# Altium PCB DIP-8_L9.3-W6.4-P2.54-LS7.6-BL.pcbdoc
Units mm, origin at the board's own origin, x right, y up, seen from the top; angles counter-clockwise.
Board outline 22.59 x 22.36 mm, 2 copper layers (Top Layer, Bottom Layer), stack 0 mm thick; 1 components, 0 nets, 8 pads, 0 vias.
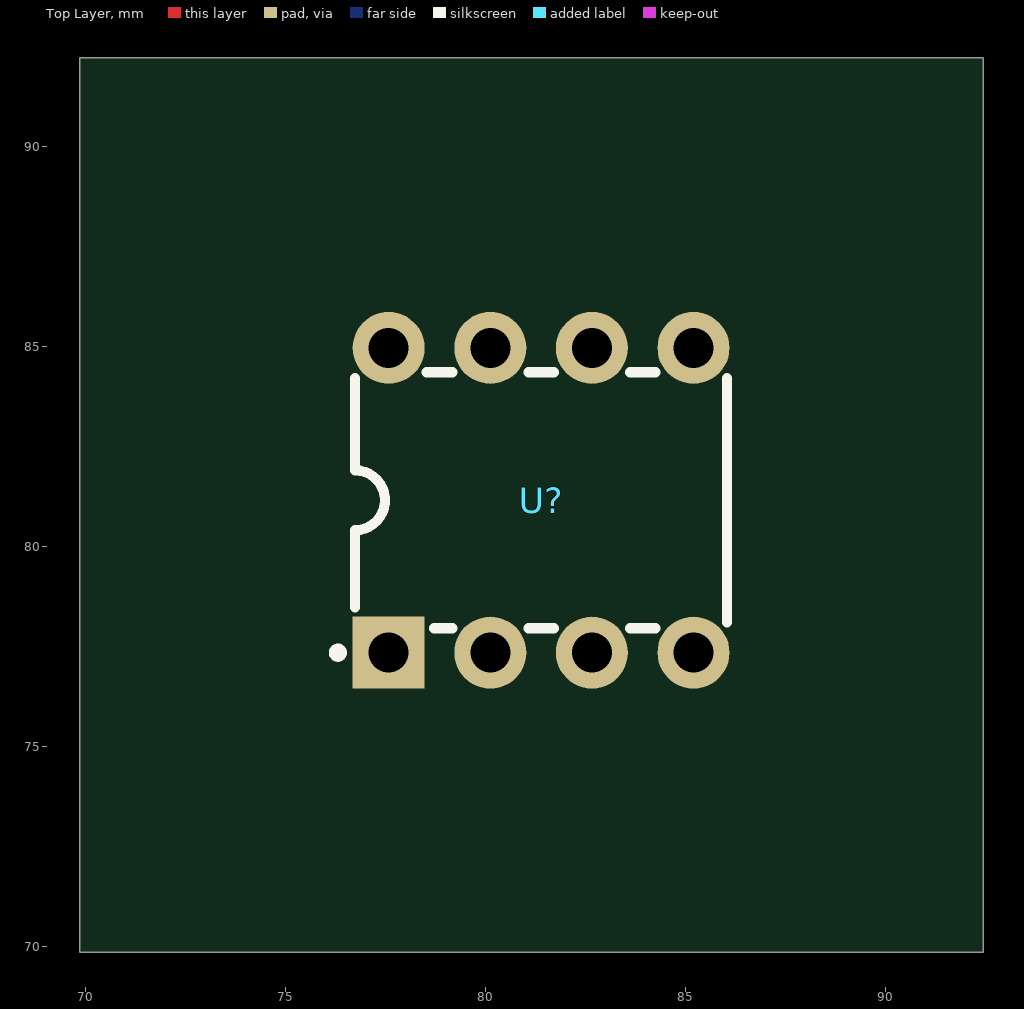
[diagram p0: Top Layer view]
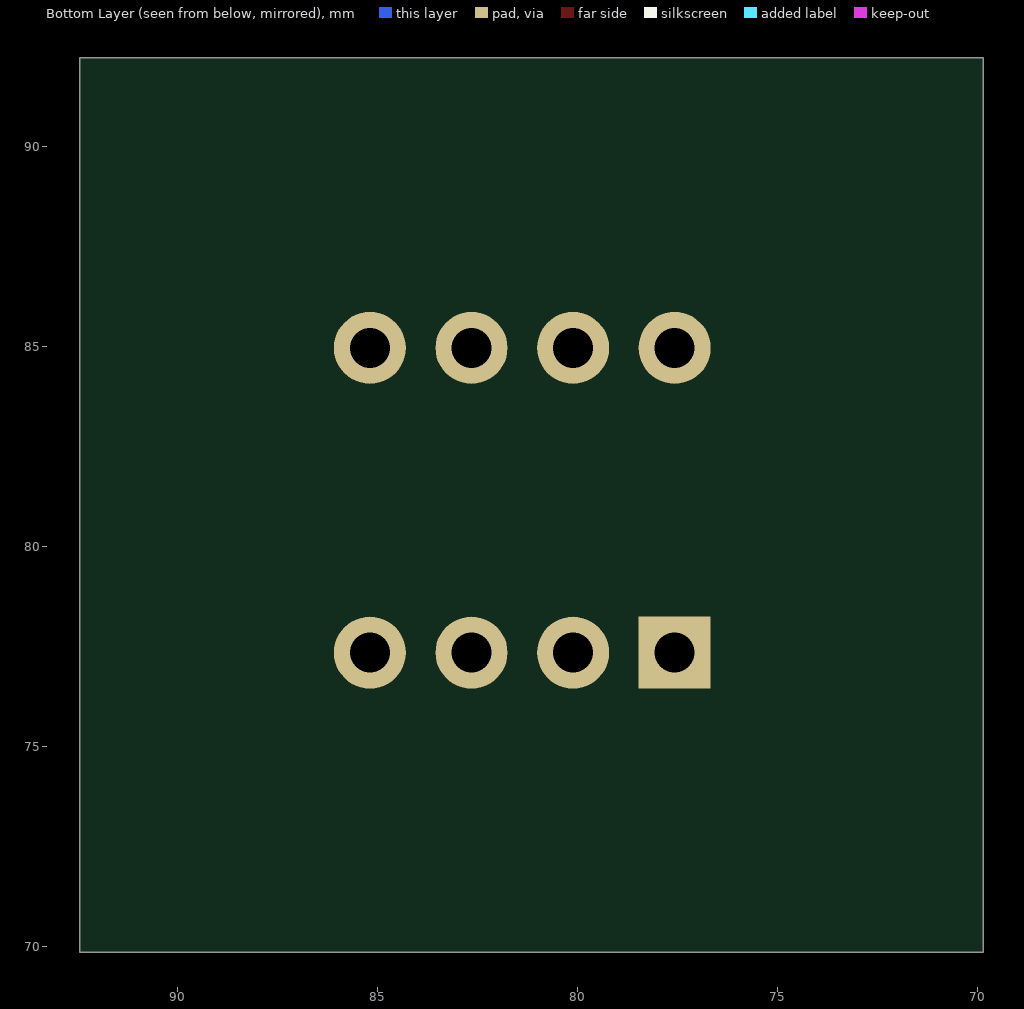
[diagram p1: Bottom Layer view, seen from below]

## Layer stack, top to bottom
Top Layer: signal copper (thickness not stored)
Bottom Layer: signal copper (thickness not stored)

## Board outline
92.44,69.85 69.85,69.85 69.85,92.209 92.44,92.209

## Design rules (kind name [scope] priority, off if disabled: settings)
PasteMaskExpansion "Paste Mask Expansion" [All] p1: expansion=0
SolderMaskExpansion "Solder Mask Expansion" [IsVia] p1: expansion=-25.4 istentingtop=TRUE
SolderMaskExpansion "Solder Mask Expansion" [All] p2: expansion=0.051 istentingtop=FALSE

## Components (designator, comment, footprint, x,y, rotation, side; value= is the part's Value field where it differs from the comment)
U? "" DIP-8_L9.3-W6.4-P2.54-LS7.6-BL 81.38,81.149 r0 top

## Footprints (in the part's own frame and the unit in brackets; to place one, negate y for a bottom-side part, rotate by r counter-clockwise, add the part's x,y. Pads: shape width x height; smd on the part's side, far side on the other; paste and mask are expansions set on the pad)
DIP-8_L9.3-W6.4-P2.54-LS7.6-BL [mm]
  rect 1.8x1.8 hole 1: 1(-3.81,-3.81)
  round 1.8 hole 1: 2(-1.27,-3.81) 3(1.27,-3.81) 4(3.81,-3.81) 5(3.81,3.81) 6(1.27,3.81) 7(-1.27,3.81) 8(-3.81,3.81)
  silkscreen extent -5.18,-3.91 4.65,3.2

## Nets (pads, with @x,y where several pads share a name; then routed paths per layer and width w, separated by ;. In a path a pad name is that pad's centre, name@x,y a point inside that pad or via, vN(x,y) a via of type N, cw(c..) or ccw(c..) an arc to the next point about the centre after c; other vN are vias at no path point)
pads on no net: U?.1 U?.2 U?.3 U?.4 U?.5 U?.6 U?.7 U?.8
